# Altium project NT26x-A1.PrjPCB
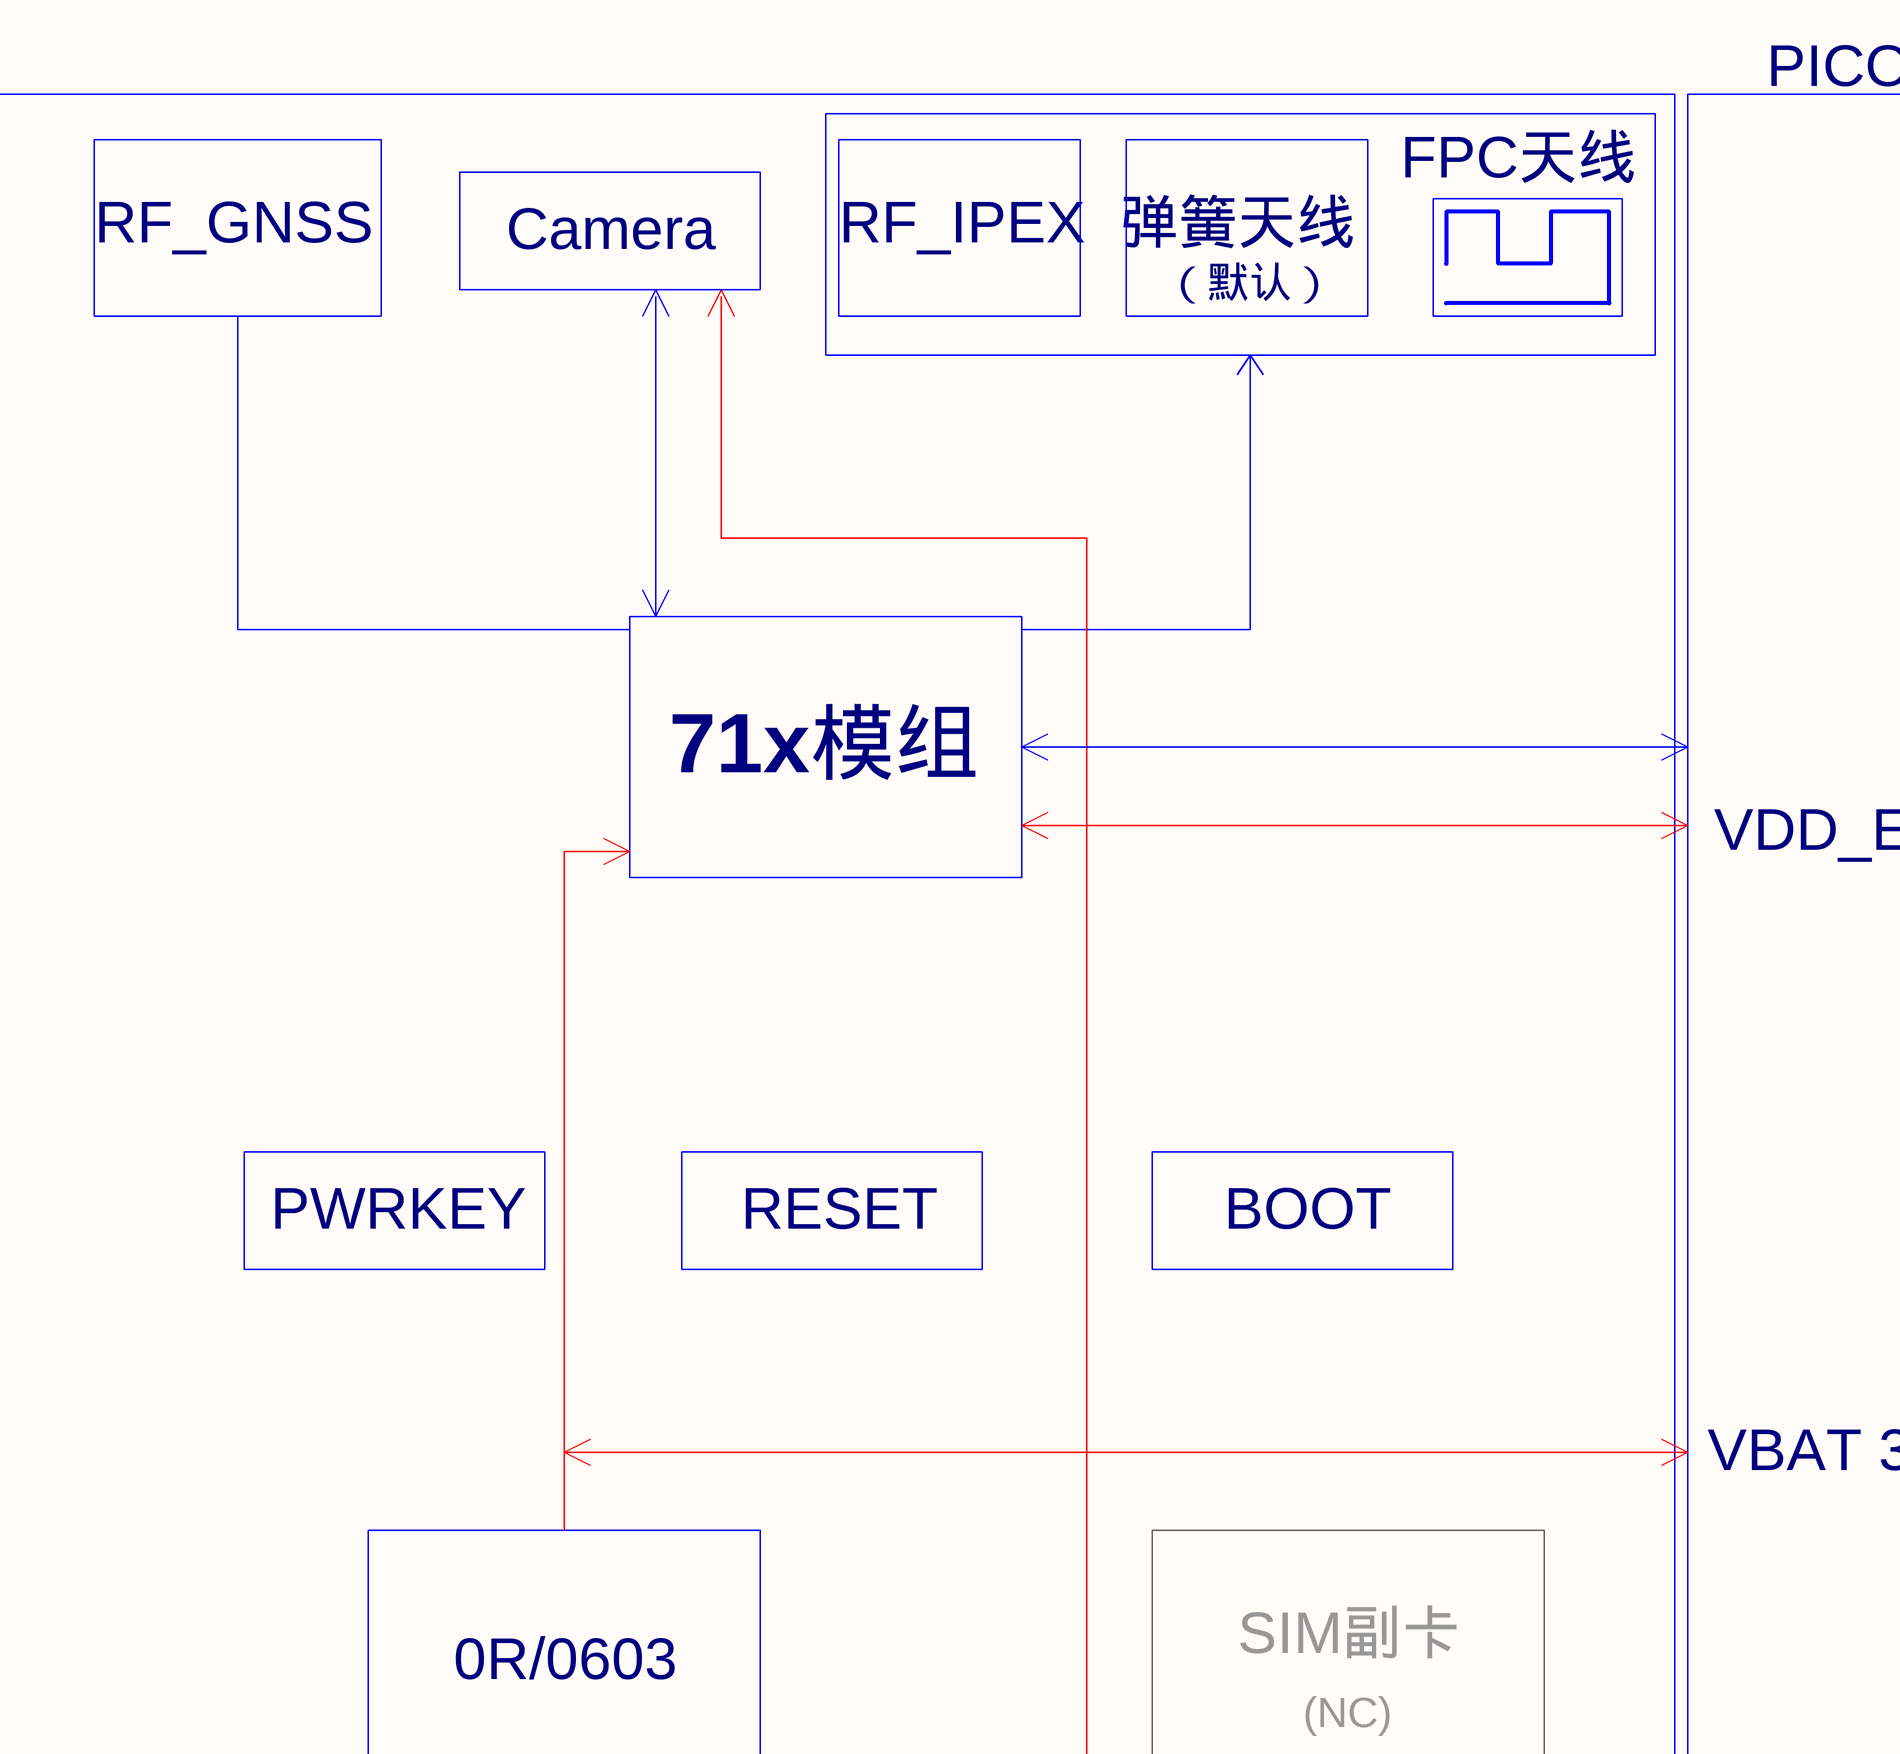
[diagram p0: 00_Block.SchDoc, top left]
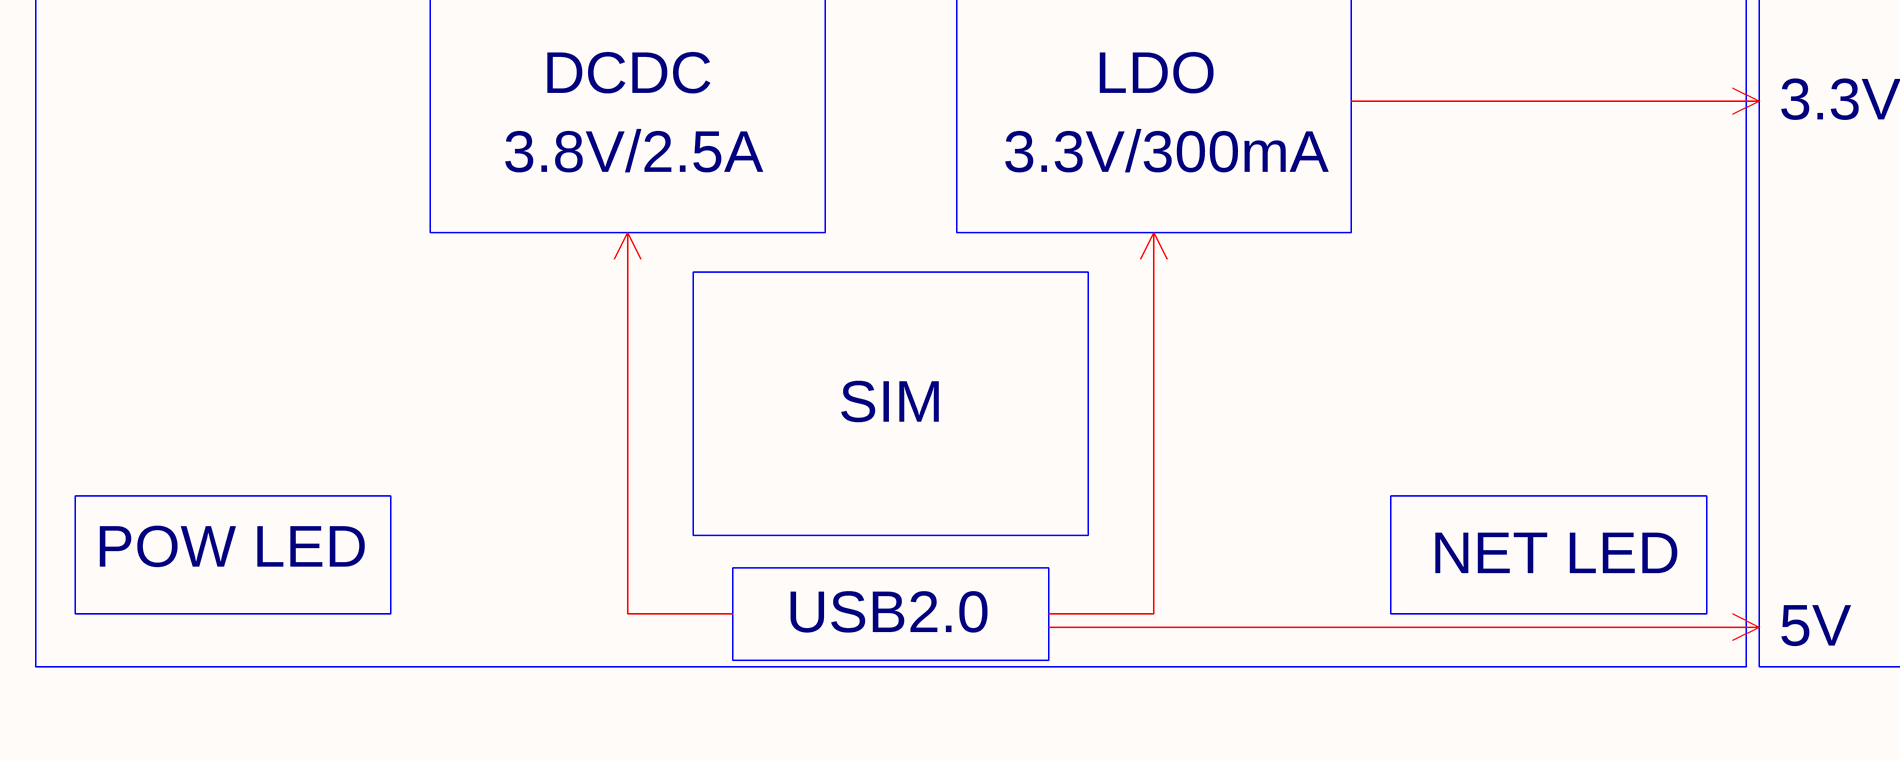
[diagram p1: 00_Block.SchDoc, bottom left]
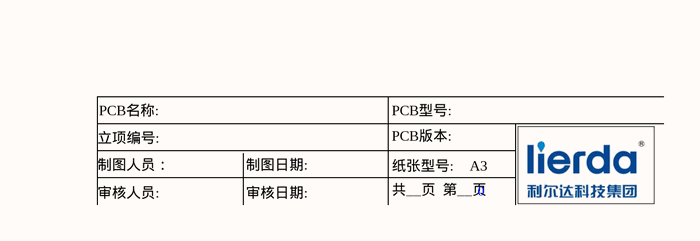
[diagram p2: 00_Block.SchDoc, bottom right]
原理图页数: 2; 版本号: V02; 项目名称: NT26-XCN系列Pico开发板; 项目型号: NT26x-A1
3 sheets, 86 parts. Net scope: global (net labels, ports and power ports of the same name join across sheets).
Board file: NT26x-A1_V02.PcbDoc
Sheets:
  00_Block.SchDoc
  01_NT26FCNB30.SchDoc
  02_Peripheral.SchDoc

## Sheet 00_Block.SchDoc
size A0

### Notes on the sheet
- PICO IO
- RF_GNSS
- RF_IPEX
- 弹簧天线
- FPC天线
- Camera
- （默认）
- 71x模组
- VDD_EXT
- PWRKEY
- RESET
- BOOT
- VBAT 3.8V
- 0R/0603
- SIM副卡
- (NC)
- DCDC
- LDO
- 3.3V
- 3.8V/2.5A
- 3.3V/300mA
- SIM
- POW LED
- NET LED
- USB2.0
- 5V
- 立项编号:
- PCB名称:
- PCB型号:
- PCB版本:
- 制图人员：
- 审核人员:
- 制图日期:
- 审核日期:
- 纸张型号:
- 共__页  第__页
- A3
- 0

## Sheet 01_NT26FCNB30.SchDoc
size A2
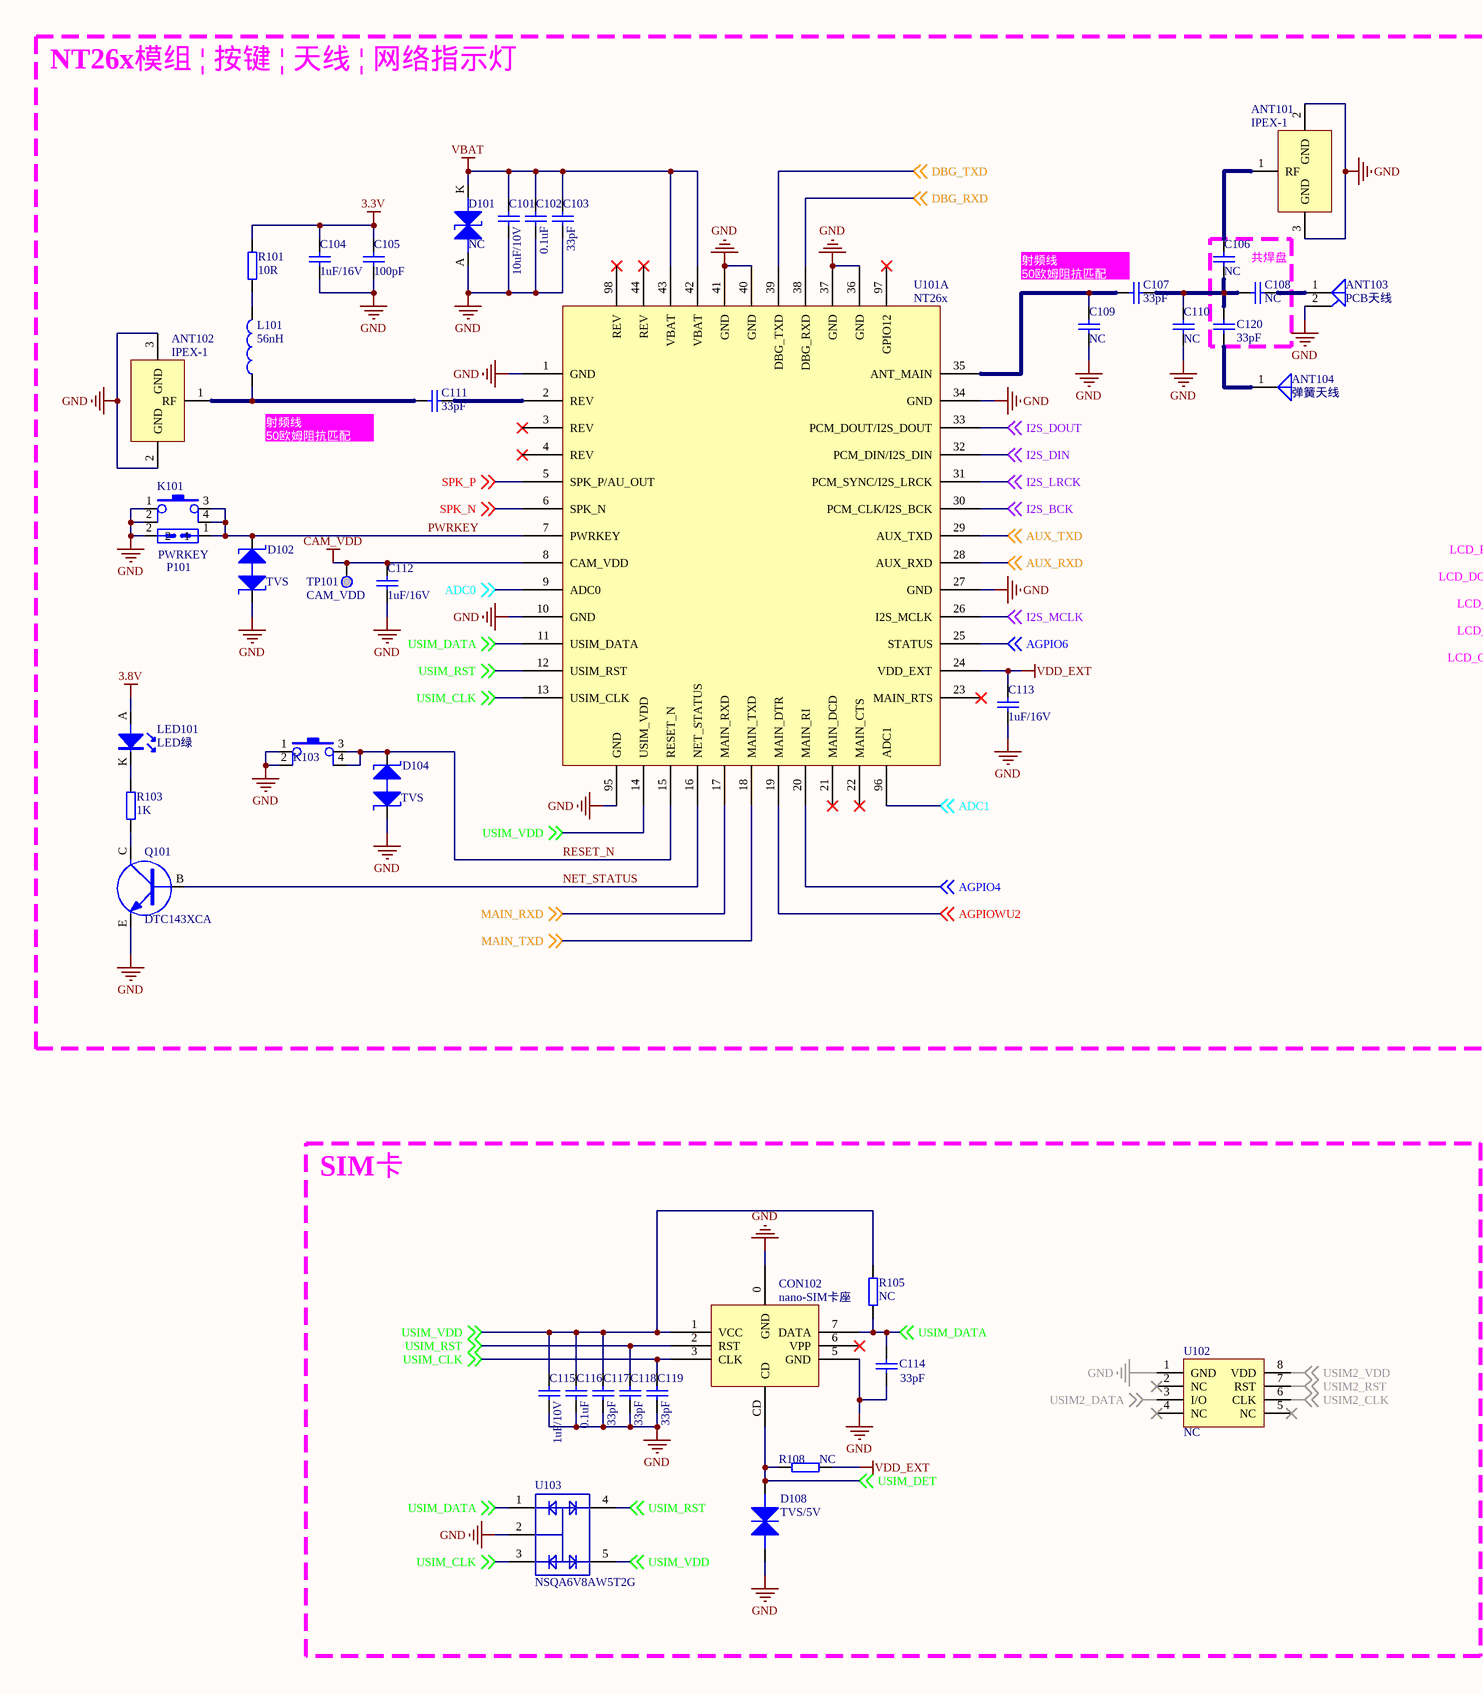
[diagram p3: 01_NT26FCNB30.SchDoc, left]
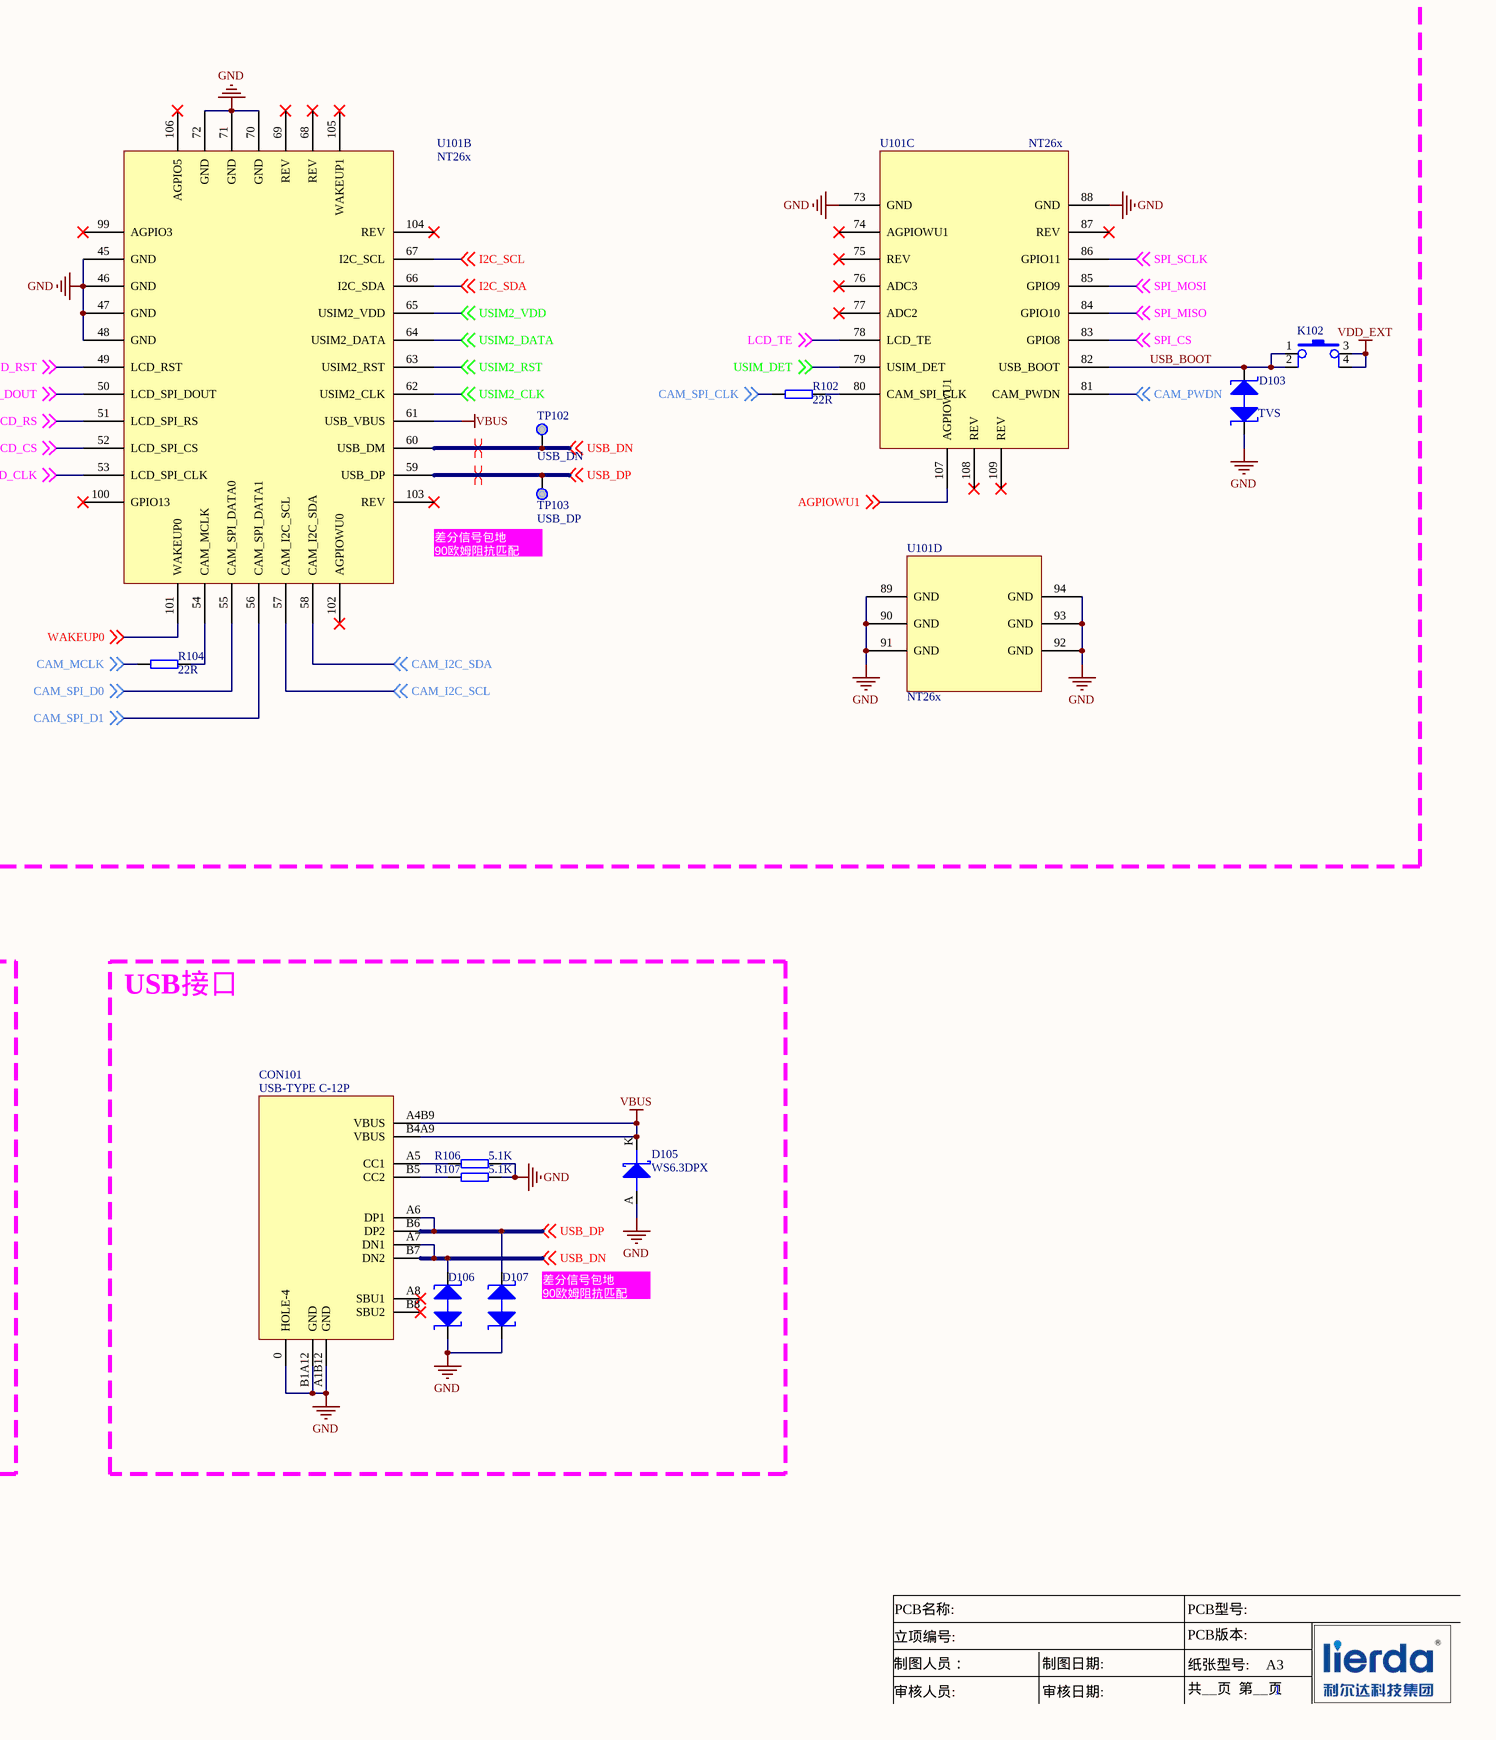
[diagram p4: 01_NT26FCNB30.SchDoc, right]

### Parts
ANT101  IPEX-1  [IPX_U.FL-R-SMT-1]
ANT102  IPEX-1  [IPX_U.FL-R-SMT-1]
ANT103  PCB天线  [ANT]
ANT104  弹簧天线  [SPG-0.8]
C101  10uF/10V  [0402C_0.4D]
C102  0.1uF  [0402C_0.4D]
C103  33pF  [0402C_0.4D]
C104  1uF/16V  [0402C_0.4D]
C105  100pF  [0402C_0.4D]
C106  NC  [0402C_0.4D]
C107  33pF  [0402C_0.4D]
C108  NC  [0402C_0.4D]
C109  NC  [0402C_0.4D]
C110  NC  [0402C_0.4D]
C111  33pF  [0402C_0.4D]
C112  1uF/16V  [0402C_0.4D]
C113  1uF/16V  [0402C_0.4D]
C114  33pF  [0402C_0.4D]
C115  1uF/10V  [0402C_0.4D]
C116  0.1uF  [0402C_0.4D]
C117  33pF  [0402C_0.4D]
C118  33pF  [0402C_0.4D]
C119  33pF  [0402C_0.4D]
C120  33pF  [0402C_0.4D]
CON101  USB-TYPE C-12P  [TYPEC _6PIN板]
CON102  nano-SIM卡座  [SIM-MUP-C7801]
D101  NC  [UDFN2(1610)-NP]
D102  TVS  [DFN1006-NP]
D103  TVS  [DFN1006-NP]
D104  TVS  [DFN1006-NP]
D105  产品型号: WS6.3DPX  [UDFN2(1610)]  (hidden comment: DIODE-TVS)
D106  DIODE-2TVS-2  [DFN1006-NP]  (value not drawn)
D107  DIODE-2TVS-2  [DFN1006-NP]  (value not drawn)
D108  TVS/5V  [SOD-523-NP]
K101  1414000735  [TS3443-0253B]  (value not drawn)
K102  1414000735  [TS3443-0253B]  (value not drawn)
K103  1414000735  [TS3443-0253B]  (value not drawn)
L101  56nH  [0402LX_0.4D]
LED101  LED绿  [D0603]
P101  PWRKEY  [0402R_0.4D_JP]
Q101  DTC143XCA  [SOT-23-3A]
R101  10R  [0402R_0.4D]
R102  22R  [0402R_0.4D]
R103  1K  [0402R_0.4D]
R104  22R  [0402R_0.4D]
R105  NC  [0402R_0.4D]
R106  5.1K  [0402R_0.4D]
R107  5.1K  [0402R_0.4D]
R108  NC  [0402R_0.4D]
TP101  CAM_VDD  [test]
TP102  USB_DN  [test]
TP103  USB_DP  [test]
U101  NT26x  [LSDWNTC-LY04095005_mood]  (parts A,B,C,D of 4)
U102  NC  [DFN8(1.27)-6X5]
U103  NSQA6V8AW5T2G  [SOT-323-5]

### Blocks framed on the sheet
NT26x模组 ¦ 按键 ¦ 天线 ¦ 网络指示灯: ANT101-ANT104 C101-C105 C107 C109-C113 D101-D104 K101-K103 L101 LED101 P101 Q101 R101-R104 TP101-TP103 U101
共焊盘: C106 C108 C120
SIM卡: C114-C119 CON102 D108 R105 R108 U102 U103
USB接口: CON101 D105-D107 R106 R107

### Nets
3.3V: C104.2 C105.2 R101.2
3.8V: LED101.A
CAM_VDD: C112.2 TP101.1 U101.8(CAM_VDD)
GND: ANT101.2(GND) ANT101.3(GND) ANT102.2(GND) ANT102.3(GND) ANT103.2 C101.1 C102.1 C103.1 C104.1 C105.1 C109.1 C110.1 C112.1 C113.1 C114.1 C115.1 C116.1 C117.1 C118.1 C119.1 CON101.0(HOLE-4) CON101.A1B12(GND) CON101.B1A12(GND) CON102.0(GND) CON102.5(GND) D101.A D102.A D103.A D104.A D105.A D106.A D107.A D108.K K101.1 K101.2 K103.1 K103.2 P101.2 Q101.E R106.1 R107.1 U101.1(GND) U101.10(GND) U101.27(GND) U101.34(GND) U101.36(GND) U101.37(GND) U101.40(GND) U101.41(GND) U101.45(GND) U101.46(GND) U101.47(GND) U101.48(GND) U101.70(GND) U101.71(GND) U101.72(GND) U101.73(GND) U101.88(GND) U101.89(GND) U101.90(GND) U101.91(GND) U101.92(GND) U101.93(GND) U101.94(GND) U101.95(GND) U102.1(GND) U103.2
VBAT: C101.2 C102.2 C103.2 D101.K U101.42(VBAT) U101.43(VBAT)
VBUS: CON101.A4B9(VBUS) CON101.B4A9(VBUS) D105.K U101.61(USB_VBUS)
VDD_EXT: C113.2 K102.3 K102.4 R108.1 U101.24(VDD_EXT)
ADC0: U101.9(ADC0) ; off-sheet ADC0
ADC1: U101.96(ADC1) ; off-sheet ADC1
AGPIO4: U101.20(MAIN_RI) ; off-sheet AGPIO4
AGPIO6: U101.25(STATUS) ; off-sheet AGPIO6
AGPIOWU1: U101.107(AGPIOWU1) ; off-sheet AGPIOWU1
AGPIOWU2: U101.19(MAIN_DTR) ; off-sheet AGPIOWU2
AUX_RXD: U101.28(AUX_RXD) ; off-sheet AUX_RXD
AUX_TXD: U101.29(AUX_TXD) ; off-sheet AUX_TXD
CAM_I2C_SCL: U101.57(CAM_I2C_SCL) ; off-sheet CAM_I2C_SCL
CAM_I2C_SDA: U101.58(CAM_I2C_SDA) ; off-sheet CAM_I2C_SDA
CAM_MCLK: R104.1 ; off-sheet CAM_MCLK
CAM_PWDN: U101.81(CAM_PWDN) ; off-sheet CAM_PWDN
CAM_SPI_CLK: R102.1 ; off-sheet CAM_SPI_CLK
CAM_SPI_D0: U101.55(CAM_SPI_DATA0) ; off-sheet CAM_SPI_D0
CAM_SPI_D1: U101.56(CAM_SPI_DATA1) ; off-sheet CAM_SPI_D1
DBG_RXD: U101.38(DBG_RXD) ; off-sheet DBG_RXD
DBG_TXD: U101.39(DBG_TXD) ; off-sheet DBG_TXD
I2C_SCL: U101.67(I2C_SCL) ; off-sheet I2C_SCL
I2C_SDA: U101.66(I2C_SDA) ; off-sheet I2C_SDA
I2S_BCK: U101.30(PCM_CLK/I2S_BCK) ; off-sheet I2S_BCK
I2S_DIN: U101.32(PCM_DIN/I2S_DIN) ; off-sheet I2S_DIN
I2S_DOUT: U101.33(PCM_DOUT/I2S_DOUT) ; off-sheet I2S_DOUT
I2S_LRCK: U101.31(PCM_SYNC/I2S_LRCK) ; off-sheet I2S_LRCK
I2S_MCLK: U101.26(I2S_MCLK) ; off-sheet I2S_MCLK
LCD_CLK: U101.53(LCD_SPI_CLK) ; off-sheet LCD_CLK
LCD_CS: U101.52(LCD_SPI_CS) ; off-sheet LCD_CS
LCD_DOUT: U101.50(LCD_SPI_DOUT) ; off-sheet LCD_DOUT
LCD_RS: U101.51(LCD_SPI_RS) ; off-sheet LCD_RS
LCD_RST: U101.49(LCD_RST) ; off-sheet LCD_RST
LCD_TE: U101.78(LCD_TE) ; off-sheet LCD_TE
MAIN_RXD: U101.17(MAIN_RXD) ; off-sheet MAIN_RXD
MAIN_TXD: U101.18(MAIN_TXD) ; off-sheet MAIN_TXD
NET_STATUS: Q101.B U101.16(NET_STATUS)
PWRKEY: D102.K K101.3 K101.4 P101.1 U101.7(PWRKEY)
RESET_N: D104.K K103.3 K103.4 U101.15(RESET_N)
SPI_CS: U101.83(GPIO8) ; off-sheet SPI_CS
SPI_MISO: U101.84(GPIO10) ; off-sheet SPI_MISO
SPI_MOSI: U101.85(GPIO9) ; off-sheet SPI_MOSI
SPI_SCLK: U101.86(GPIO11) ; off-sheet SPI_SCLK
SPK_N: U101.6(SPK_N) ; off-sheet SPK_N
SPK_P: U101.5(SPK_P/AU_OUT) ; off-sheet SPK_P
USB_BOOT: D103.K K102.1 K102.2 U101.82(USB_BOOT)
USB_DN: CON101.A7(DN1) CON101.B7(DN2) D106.K TP102.1 U101.60(USB_DM) ; off-sheet USB_DN
USB_DP: CON101.A6(DP1) CON101.B6(DP2) D107.K TP103.1 U101.59(USB_DP) ; off-sheet USB_DP
USIM2_CLK: U101.62(USIM2_CLK) U102.6(CLK) ; off-sheet USIM2_CLK
USIM2_DATA: U101.64(USIM2_DATA) U102.3(I/O) ; off-sheet USIM2_DATA
USIM2_RST: U101.63(USIM2_RST) U102.7(RST) ; off-sheet USIM2_RST
USIM2_VDD: U101.65(USIM2_VDD) U102.8(VDD) ; off-sheet USIM2_VDD
USIM_CLK: C119.2 CON102.3(CLK) U101.13(USIM_CLK) U103.3 ; off-sheet USIM_CLK
USIM_DATA: C114.2 CON102.7(DATA) R105.1 U101.11(USIM_DATA) U103.1 ; off-sheet USIM_DATA
USIM_DET: CON102.CD D108.A R108.2 U101.79(USIM_DET) ; off-sheet USIM_DET
USIM_RST: C118.2 CON102.2(RST) U101.12(USIM_RST) U103.4 ; off-sheet USIM_RST
USIM_VDD: C115.2 C116.2 C117.2 CON102.1(VCC) R105.2 U101.14(USIM_VDD) U103.5 ; off-sheet USIM_VDD
WAKEUP0: U101.101(WAKEUP0) ; off-sheet WAKEUP0
NetANT101_1: ANT101.1(RF) C106.2
NetANT102_1: ANT102.1(RF) C111.1 L101.1
NetANT103_1: ANT103.1 C108.1
NetANT104_1: ANT104.1 C120.2
NetC106_1: C106.1 C107.1 C108.2 C110.2 C120.1
NetC107_2: C107.2 C109.2 U101.35(ANT_MAIN)
NetC111_2: C111.2 U101.2(REV)
NetCON101_A5: CON101.A5(CC1) R106.2
NetCON101_B5: CON101.B5(CC2) R107.2
NetL101_2: L101.2 R101.1
NetLED101_K: LED101.K R103.1
NetQ101_C: Q101.C R103.2
NetR102_2: R102.2 U101.80(CAM_SPI_CLK)
NetR104_2: R104.2 U101.54(CAM_MCLK)

Not connected (* = marked no-connect by the designer): CON101 A8(SBU1)* B8(SBU2)*; CON102 6(VPP)*; U101 3(REV)* 4(REV)* 21(MAIN_DCD)* 22(MAIN_CTS)* 23(MAIN_RTS)* 44(REV)* 68(REV)* 69(REV)* 74(AGPIOWU1)* 75(REV)* 76(ADC3)* 77(ADC2)* 87(REV)* 97(GPIO12)* 98(REV)* 99(AGPIO3)* 100(GPIO13)* 102(AGPIOWU0)* 103(REV)* 104(REV)* 105(WAKEUP1)* 106(AGPIO5)* 108(REV)* 109(REV)*; U102 2(NC)* 4(NC)* 5(NC)*

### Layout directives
differential pair: USB_DN, USB_DP

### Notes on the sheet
- (near C107) 射频线
  50欧姆阻抗匹配
- 射频线
  50欧姆阻抗匹配
- 差分信号包地
  90欧姆阻抗匹配
- (near D107) 差分信号包地
  90欧姆阻抗匹配
- PCB名称:
- PCB型号:
- 制图人员：
- 审核人员:
- 立项编号:
- 制图日期:
- 审核日期:
- PCB版本:
- 纸张型号:
- 共__页  第__页
- A3
- 1

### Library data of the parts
ANT101 ANT102 = 1416000325: DC-6GHz; 产品型号: SL2-240006-A; 品名: RF测试座; 原厂品牌: 森岭; 封装: SMD; 物料状态: 优选
ANT103 = ANT 2P: PCB/陶瓷/铁件天线
ANT104 = 1417001013: 5.0/10.5/0.8; 产品型号: SLEingE100020432; 原厂品牌: 森岭; 封装: DIP; 物料状态: 优选
C101 = 1405001308: 10uF/10V/20%/X5R; 产品型号: CL05A106MP5NUNC; 品名: 陶瓷电容; 原厂品牌: SAMSUNG电容; 封装: 0402; 物料状态: 优选
C102 C116 = 1405000041: 0.1uF/16V/10%/X7R; 产品型号: CC0402KRX7R7BB104; 品名: 陶瓷电容; 原厂品牌: YAGEO; 封装: 0402; 物料状态: 优选
C103 C106-C111 C114 C117-C120 = 1405000291: 33pF/50V/5%/C0G; 产品型号: CC0402JRNPO9BN330; 品名: 陶瓷电容; 原厂品牌: YAGEO; 封装: 0402; 物料状态: 优选
C104 C112 C113 = 1405004038: 1uF/16V/10%/X5R; 产品型号: CL05A105KO5NNNC; 品名: 陶瓷电容; 原厂品牌: SAMSUNG电容; 封装: 0402; 物料状态: 优选
C105 = 1405000254: 100pF/50V/5%/C0G; 产品型号: CC0402JRNPO9BN101; 品名: 陶瓷电容; 原厂品牌: YAGEO; 封装: 0402; 物料状态: 优选
C115 = 1405001767: 1uF/10V/10%/X5R; 产品型号: CL05A105KP5NNNC; 品名: 陶瓷电容; 原厂品牌: SAMSUNG电容; 封装: 0402; 物料状态: 优选
CON101 = 1416003448: USB Type-C; 产品型号: U20405-2; 封装: SMD; 品名: USB连接器; 物料状态: 优选; 原厂品牌: 德海威
CON102 = 1416003211: Push-Push NANO-SIM Card Connector; 产品型号: MUP-C7801-2; 品名: 卡座连接器; 原厂品牌: 德海威; 封装: SMD; 物料状态: 优选
D101 = 1409003027: 双向; 产品型号: ESD56151D04-2/TR; 器件名称: TVS管; 原厂品牌: Willsemi; 封装: DFN1610-2L
D102-D104 = 1409004149: 1通道; 产品型号: WS05DPF-BH; 品名: ESD保护器件; 原厂品牌: WAYON（维安）; 封装: DFN1006-2L; 物料状态: 优选
D105 = 1409004319: 1通道; 品名: ESD保护器件; 原厂品牌: WAYON（维安）; 封装: DFN1610-2L; 物料状态: 优选
D106 D107 = 1409004148: 1通道; 产品型号: WS6183KF; 品名: ESD保护器件; 原厂品牌: WAYON（维安）; 封装: DFN1006-2L; 物料状态: 优选
D108 = 1409000207: ESD保护/双向; 器件名称: 二极管; 原厂品牌: Nexperia; 封装: SOD523
K101-K103 = 1416003591: 6*6*7.3; 产品型号: JY-TS6060-H7.3-AA26F; 品名: 轻触开关; 原厂品牌: 温达; 封装: SMD; 物料状态: 优选
L101 = 1404000107: 56nH/2%/200mA/1.17Ω; 产品型号: LQW15AN56NG00D; 品名: 绕线电感; 原厂品牌: MURATA; 封装: 0402; 物料状态: 优选
LED101 = 1409000351: 绿/25mA/112-285mcd; 产品型号: 19-217/GHC-YR1S2/6T; 品名: LED发光二极管; 原厂品牌: EVERLIGHT; 封装: 0603; 物料状态: 优选
P101 = JP2Q: 短路帽
Q101 = 1412002409: NPN/0.1A/50V/200mW; 品名: 三极管; 原厂品牌: YJ; 封装: SOT-23; 物料状态: 优选
R101 = 1408001194: 10R/1%; 产品型号: RC0402FR-0710RL; 品名: 厚膜贴片电阻; 原厂品牌: YAGEO; 封装: 0402; 物料状态: 优选
R102 R104 = 1408001926: 22R/5%; 产品型号: RJ0402-22R; 品名: 厚膜贴片电阻; 原厂品牌: Uniohm; 封装: 0402; 物料状态: 优选
R103 = 1408000156: 1K/5%; 产品型号: RC0402JR-071KL; 品名: 厚膜贴片电阻; 原厂品牌: YAGEO; 封装: 0402; 物料状态: 优选
R105 R108 = 1408000158: 10K/5%; 产品型号: RC0402JR-0710KL; 品名: 厚膜贴片电阻; 原厂品牌: YAGEO; 封装: 0402; 物料状态: 优选
R106 R107 = 1408001063: 5.1K/5%; 产品型号: RC0402JR-075K1L; 品名: 厚膜贴片电阻; 原厂品牌: YAGEO; 封装: 0402; 物料状态: 优选
TP101-TP103 = MARK
U101 = NT26F Y0A-P-B01
U102 = 180006-03G: 存货编码: 1410013522; 封装: MFF2; 型号: 28991070003-FA; 品牌: 不指定（客供料）
U103 = 1409000217: 双向/7.14V/600W; 器件名称: TVS管; 原厂品牌: Onsemi

## Sheet 02_Peripheral.SchDoc
size A3
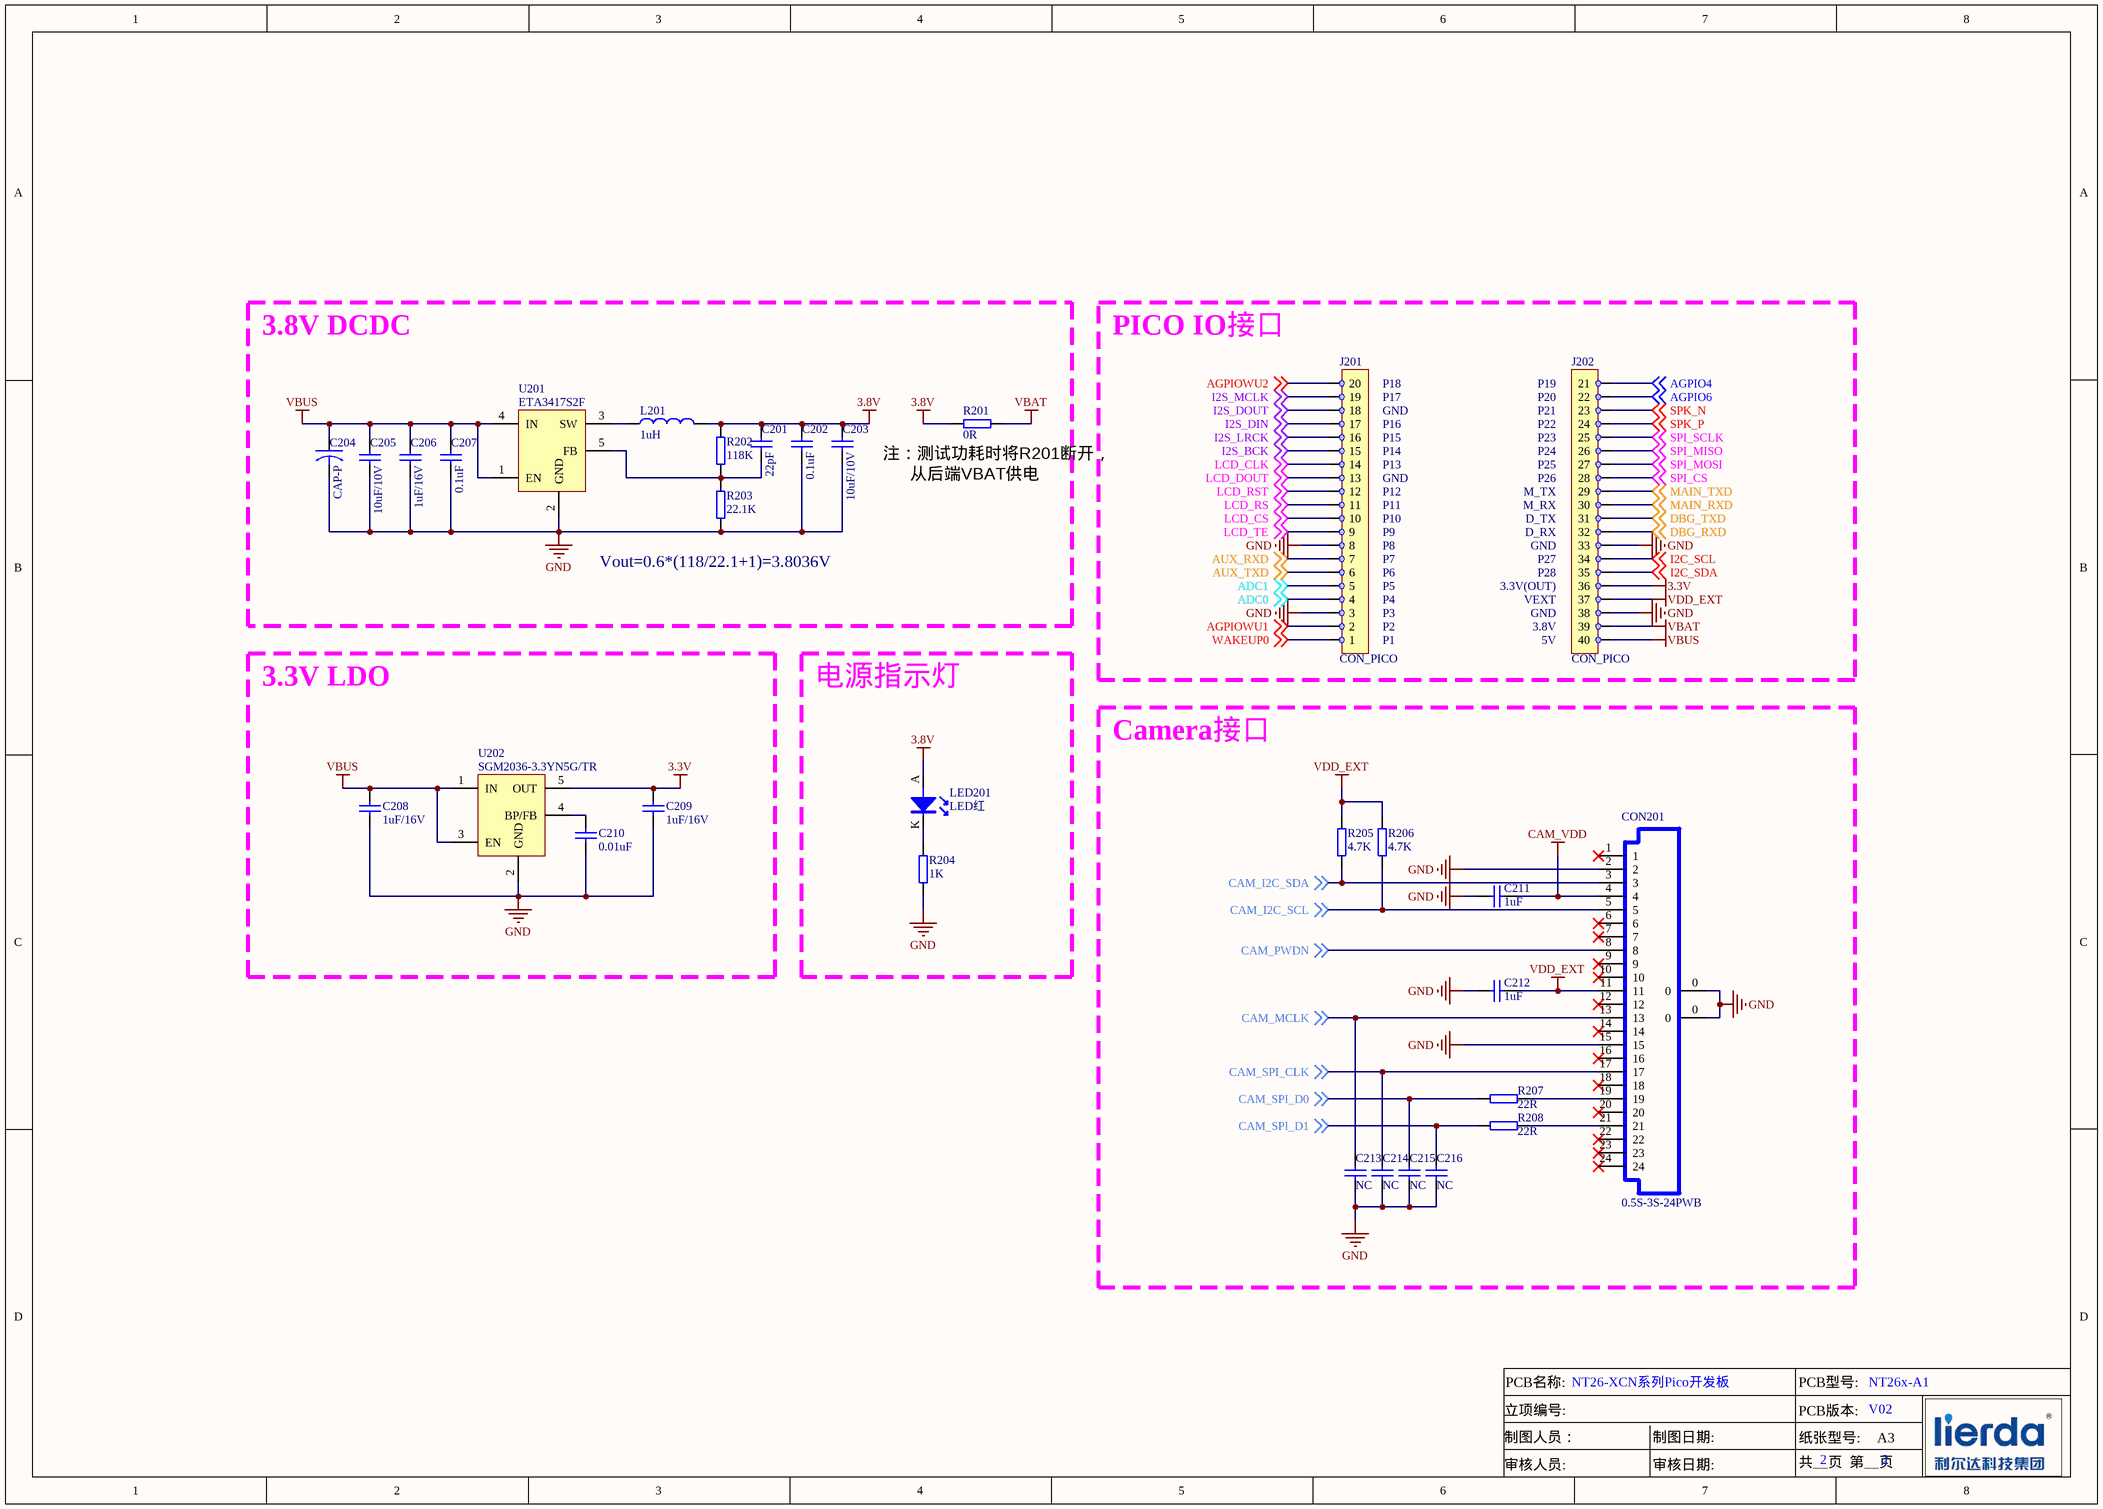
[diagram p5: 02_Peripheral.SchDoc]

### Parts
C201  22pF  [0402C_0.4D]
C202  0.1uF  [0402C_0.4D]
C203  10uF/10V  [0402C_0.4D]
C204  CAP-P  [3528-TB]
C205  10uF/10V  [0402C_0.4D]
C206  1uF/16V  [0402C_0.4D]
C207  0.1uF  [0402C_0.4D]
C208  1uF/16V  [0402C_0.4D]
C209  1uF/16V  [0402C_0.4D]
C210  0.01uF  [0402C_0.4D]
C211  1uF  [0402C_0.4D]
C212  1uF  [0402C_0.4D]
C213  NC  [0402C_0.4D]
C214  NC  [0402C_0.4D]
C215  NC  [0402C_0.4D]
C216  NC  [0402C_0.4D]
CON201  产品型号: 0.5S-3S-24PWB  [FPC0.5S-24P]  (hidden comment: FPC-24)
J201  CON_PICO  [J201_半孔与排针]
J202  CON_PICO  [J202_半孔与排针]
L201  1uH  [0806L_0.6D]
LED201  LED红  [D0603]
R201  0R  [0603R_0.6D]
R202  118K  [0402R_0.4D]
R203  22.1K  [0402R_0.4D]
R204  1K  [0402R_0.4D]
R205  4.7K  [0402R_0.4D]
R206  4.7K  [0402R_0.4D]
R207  22R  [0402R_0.4D]
R208  22R  [0402R_0.4D]
U201  ETA3417S2F  [SOT-23-5P]
U202  产品型号: SGM2036-3.3YN5G/TR  [SOT-23-5P]  (hidden comment: SGM2036-XYN5G/TR)

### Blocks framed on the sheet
3.8V DCDC: C201-C207 L201 R201-R203 U201
PICO IO接口: J201 J202
3.3V LDO: C208-C210 U202
电源指示灯: LED201 R204
Camera接口: C211-C216 CON201 R205-R208

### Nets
3.3V: C209.2 J202.36 U202.5(OUT)
3.8V: C201.2 C202.2 C203.2 L201.2 LED201.A R201.1 R202.2
CAM_VDD: C211.1 CON201.4
GND: C202.1 C203.1 C204.2 C205.1 C206.1 C207.1 C208.1 C209.1 C210.1 C211.2 C212.2 C213.1 C214.1 C215.1 C216.1 CON201.0 CON201.2 CON201.15 J201.3 J201.8 J202.33 J202.38 R203.2 R204.2 U201.2(GND) U202.2(GND)
VBAT: J202.39 R201.2
VBUS: C204.1 C205.2 C206.2 C207.2 C208.2 J202.40 U201.1(EN) U201.4(IN) U202.1(IN) U202.3(EN)
VDD_EXT: C212.1 CON201.11 J202.37 R205.2 R206.2
ADC0: J201.4 ; off-sheet ADC0
ADC1: J201.5 ; off-sheet ADC1
AGPIO4: J202.21 ; off-sheet AGPIO4
AGPIO6: J202.22 ; off-sheet AGPIO6
AGPIOWU1: J201.2 ; off-sheet AGPIOWU1
AGPIOWU2: J201.20 ; off-sheet AGPIOWU2
AUX_RXD: J201.7 ; off-sheet AUX_RXD
AUX_TXD: J201.6 ; off-sheet AUX_TXD
CAM_I2C_SCL: CON201.5 R206.1 ; off-sheet CAM_I2C_SCL
CAM_I2C_SDA: CON201.3 R205.1 ; off-sheet CAM_I2C_SDA
CAM_MCLK: C213.2 CON201.13 ; off-sheet CAM_MCLK
CAM_PWDN: CON201.8 ; off-sheet CAM_PWDN
CAM_SPI_CLK: C214.2 CON201.17 ; off-sheet CAM_SPI_CLK
CAM_SPI_D0: C215.2 R207.1 ; off-sheet CAM_SPI_D0
CAM_SPI_D1: C216.2 R208.1 ; off-sheet CAM_SPI_D1
DBG_RXD: J202.32 ; off-sheet DBG_RXD
DBG_TXD: J202.31 ; off-sheet DBG_TXD
I2C_SCL: J202.34 ; off-sheet I2C_SCL
I2C_SDA: J202.35 ; off-sheet I2C_SDA
I2S_BCK: J201.15 ; off-sheet I2S_BCK
I2S_DIN: J201.17 ; off-sheet I2S_DIN
I2S_DOUT: J201.18 ; off-sheet I2S_DOUT
I2S_LRCK: J201.16 ; off-sheet I2S_LRCK
I2S_MCLK: J201.19 ; off-sheet I2S_MCLK
LCD_CLK: J201.14 ; off-sheet LCD_CLK
LCD_CS: J201.10 ; off-sheet LCD_CS
LCD_DOUT: J201.13 ; off-sheet LCD_DOUT
LCD_RS: J201.11 ; off-sheet LCD_RS
LCD_RST: J201.12 ; off-sheet LCD_RST
LCD_TE: J201.9 ; off-sheet LCD_TE
MAIN_RXD: J202.30 ; off-sheet MAIN_RXD
MAIN_TXD: J202.29 ; off-sheet MAIN_TXD
SPI_CS: J202.28 ; off-sheet SPI_CS
SPI_MISO: J202.26 ; off-sheet SPI_MISO
SPI_MOSI: J202.27 ; off-sheet SPI_MOSI
SPI_SCLK: J202.25 ; off-sheet SPI_SCLK
SPK_N: J202.23 ; off-sheet SPK_N
SPK_P: J202.24 ; off-sheet SPK_P
WAKEUP0: J201.1 ; off-sheet WAKEUP0
NetC201_1: C201.1 R202.1 R203.1 U201.5(FB)
NetC210_2: C210.2 U202.4(BP/FB)
NetCON201_19: CON201.19 R207.2
NetCON201_21: CON201.21 R208.2
NetL201_1: L201.1 U201.3(SW)
NetLED201_K: LED201.K R204.1

Not connected (* = marked no-connect by the designer): CON201 1* 6* 7* 9* 10* 12* 14* 16* 18* 20* 22* 23* 24*

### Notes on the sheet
- (near J201) P18
- (near J202) P19
- (near J201) P14
- (near J201) P15
- (near J201) P16
- (near J201) P17
- (near J201) GND
- (near J202) P24
- (near J202) P23
- (near J202) P22
- (near J202) P21
- (near J202) P20
- (near R201) 注：测试功耗时将R201断开，
- (near R201) 从后端VBAT供电
- (near J201) P10
- (near J201) P11
- (near J201) P12
- (near J201) P13
- (near J202) M_TX
- (near J202) M_RX
- (near J202) D_TX
- (near J202) P26
- (near J202) P25
- (near R203) Vout=0.6*(118/22.1+1)=3.8036V
- (near J201) P5
- (near J201) P6
- (near J201) P7
- (near J201) P8
- (near J201) P9
- (near J202) D_RX
- (near J202) P27
- (near J202) P28
- (near J202) GND
- (near J202) 3.3V(OUT)
- (near J201) P1
- (near J201) P2
- (near J201) P3
- (near J201) P4
- (near J202) 5V
- (near J202) VEXT
- (near J202) 3.8V
- 2

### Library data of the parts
C201 = 1405000255: 22pF/50V/5%/C0G; 产品型号: CC0402JRNPO9BN220; 品名: 陶瓷电容; 原厂品牌: YAGEO; 封装: 0402; 物料状态: 优选
C202 C207 = 1405000041: as C102 on sheet 01_NT26FCNB30
C203 C205 = 1405001308: as C101 on sheet 01_NT26FCNB30
C204 = 1405001402: 220uF/6.3V/20%/35mΩ; 产品型号: TCOB0J227M8R-EN2; 品名: 钽电容; 原厂品牌: ROHM; 封装: B型; 物料状态: 限用
C206 C208 C209 = 1405004038: as C104 on sheet 01_NT26FCNB30
C210 = 1405000289: 10nF/50V/10%/X7R; 产品型号: CC0402KRX7R9BB103; 品名: 陶瓷电容; 原厂品牌: YAGEO; 封装: 0402; 物料状态: 优选
C211 C212 = 1405001767: as C115 on sheet 01_NT26FCNB30
C213-C216 = 1405000291: as C103 on sheet 01_NT26FCNB30
CON201 = 1416001709: 0.50mm/24PIN; 品名: FFC，FPC连接器; 原厂品牌: 乐清华宝; 封装: SMD; 物料状态: 优选
J201 J202 = 1416002098: 2.54mm/1*20PIN/直; 产品型号: PH2.54排针1*20P/L=11.5PA=6.0PC=3.0; 存货编码: 1416002080; 品名: 排针; 原厂品牌: 联益; 封装: DIP; 物料状态: 优选
L201 = 1404002051: 1uH/20%/2*1.6*1/2.9A/0.06Ω; 产品型号: WIP201610P-1R0ML; 品名: 功率电感; 原厂品牌: 佳邦（电感）; 封装: 0806; 物料状态: 优选
LED201 = 1409000426: 红/25mA/54mcd; 产品型号: 19-213SURC/S530-A2/5T; 品名: LED发光二极管; 原厂品牌: EVERLIGHT; 封装: 0603; 物料状态: 优选
R201 = 1408000425: 0R/1%; 产品型号: 0603WAF0000T5E; 品名: 厚膜贴片电阻; 原厂品牌: Uniohm; 封装: 0603; 物料状态: 优选
R202 = 1408006755: 118K/1%; 产品型号: RC0402FR-07118KL; 品名: 厚膜贴片电阻; 原厂品牌: YAGEO; 封装: 0402; 物料状态: 优选
R203 = 1408006226: 22.1K/1%; 产品型号: RC0402FR-0722K1L; 品名: 厚膜贴片电阻; 原厂品牌: YAGEO; 封装: 0402; 物料状态: 优选
R204 = 1408000156: as R103 on sheet 01_NT26FCNB30
R205 R206 = 1408000467: 4.7K/5%; 产品型号: RC0402JR-074K7L; 品名: 厚膜贴片电阻; 原厂品牌: YAGEO; 封装: 0402; 物料状态: 优选
R207 R208 = 1408001926: as R102 on sheet 01_NT26FCNB30
U201 = 1407003604: 2.6-7V/0.6-7V/2.5A/3MHz/Buck; 品名: DC-DC芯片; 原厂品牌: 钰泰科技; 封装: SOT-23-5; 物料状态: 优选
U202 = 1407000926: 3.3V/300mA/1.6-5.5V; 品名: 低压差线性稳压器; 原厂品牌: 圣邦微; 封装: SOT-23-5; 物料状态: 优选

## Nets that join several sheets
3.3V: 01_NT26FCNB30 (C104.2 C105.2 R101.2), 02_Peripheral (C209.2 J202.36 U202.5)
3.8V: 01_NT26FCNB30 (LED101.A), 02_Peripheral (7 pins)
CAM_VDD: 01_NT26FCNB30 (C112.2 TP101.1 U101.8), 02_Peripheral (C211.1 CON201.4)
GND: 01_NT26FCNB30 (67 pins), 02_Peripheral (26 pins)
VBAT: 01_NT26FCNB30 (6 pins), 02_Peripheral (J202.39 R201.2)
VBUS: 01_NT26FCNB30 (CON101.A4B9 CON101.B4A9 D105.K U101.61), 02_Peripheral (10 pins)
VDD_EXT: 01_NT26FCNB30 (5 pins), 02_Peripheral (5 pins)
ADC0: 01_NT26FCNB30 (U101.9), 02_Peripheral (J201.4)
ADC1: 01_NT26FCNB30 (U101.96), 02_Peripheral (J201.5)
AGPIO4: 01_NT26FCNB30 (U101.20), 02_Peripheral (J202.21)
AGPIO6: 01_NT26FCNB30 (U101.25), 02_Peripheral (J202.22)
AGPIOWU1: 01_NT26FCNB30 (U101.107), 02_Peripheral (J201.2)
AGPIOWU2: 01_NT26FCNB30 (U101.19), 02_Peripheral (J201.20)
AUX_RXD: 01_NT26FCNB30 (U101.28), 02_Peripheral (J201.7)
AUX_TXD: 01_NT26FCNB30 (U101.29), 02_Peripheral (J201.6)
CAM_I2C_SCL: 01_NT26FCNB30 (U101.57), 02_Peripheral (CON201.5 R206.1)
CAM_I2C_SDA: 01_NT26FCNB30 (U101.58), 02_Peripheral (CON201.3 R205.1)
CAM_MCLK: 01_NT26FCNB30 (R104.1), 02_Peripheral (C213.2 CON201.13)
CAM_PWDN: 01_NT26FCNB30 (U101.81), 02_Peripheral (CON201.8)
CAM_SPI_CLK: 01_NT26FCNB30 (R102.1), 02_Peripheral (C214.2 CON201.17)
CAM_SPI_D0: 01_NT26FCNB30 (U101.55), 02_Peripheral (C215.2 R207.1)
CAM_SPI_D1: 01_NT26FCNB30 (U101.56), 02_Peripheral (C216.2 R208.1)
DBG_RXD: 01_NT26FCNB30 (U101.38), 02_Peripheral (J202.32)
DBG_TXD: 01_NT26FCNB30 (U101.39), 02_Peripheral (J202.31)
I2C_SCL: 01_NT26FCNB30 (U101.67), 02_Peripheral (J202.34)
I2C_SDA: 01_NT26FCNB30 (U101.66), 02_Peripheral (J202.35)
I2S_BCK: 01_NT26FCNB30 (U101.30), 02_Peripheral (J201.15)
I2S_DIN: 01_NT26FCNB30 (U101.32), 02_Peripheral (J201.17)
I2S_DOUT: 01_NT26FCNB30 (U101.33), 02_Peripheral (J201.18)
I2S_LRCK: 01_NT26FCNB30 (U101.31), 02_Peripheral (J201.16)
I2S_MCLK: 01_NT26FCNB30 (U101.26), 02_Peripheral (J201.19)
LCD_CLK: 01_NT26FCNB30 (U101.53), 02_Peripheral (J201.14)
LCD_CS: 01_NT26FCNB30 (U101.52), 02_Peripheral (J201.10)
LCD_DOUT: 01_NT26FCNB30 (U101.50), 02_Peripheral (J201.13)
LCD_RS: 01_NT26FCNB30 (U101.51), 02_Peripheral (J201.11)
LCD_RST: 01_NT26FCNB30 (U101.49), 02_Peripheral (J201.12)
LCD_TE: 01_NT26FCNB30 (U101.78), 02_Peripheral (J201.9)
MAIN_RXD: 01_NT26FCNB30 (U101.17), 02_Peripheral (J202.30)
MAIN_TXD: 01_NT26FCNB30 (U101.18), 02_Peripheral (J202.29)
SPI_CS: 01_NT26FCNB30 (U101.83), 02_Peripheral (J202.28)
SPI_MISO: 01_NT26FCNB30 (U101.84), 02_Peripheral (J202.26)
SPI_MOSI: 01_NT26FCNB30 (U101.85), 02_Peripheral (J202.27)
SPI_SCLK: 01_NT26FCNB30 (U101.86), 02_Peripheral (J202.25)
SPK_N: 01_NT26FCNB30 (U101.6), 02_Peripheral (J202.23)
SPK_P: 01_NT26FCNB30 (U101.5), 02_Peripheral (J202.24)
WAKEUP0: 01_NT26FCNB30 (U101.101), 02_Peripheral (J201.1)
